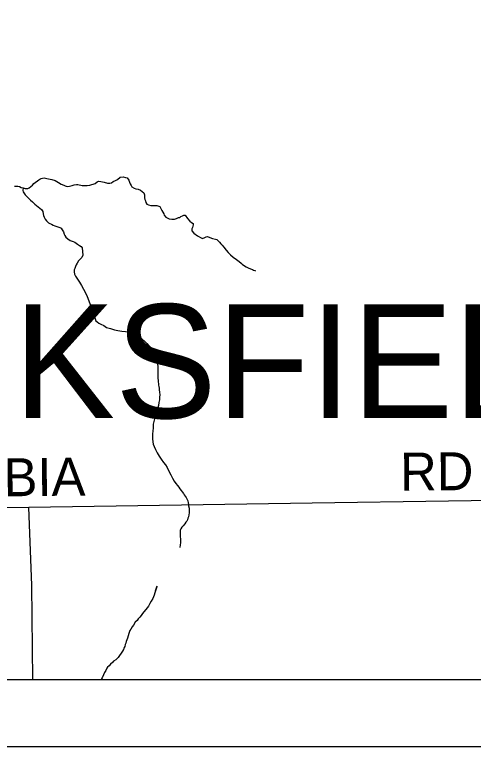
# Model space of a CAD drawing. Extents: x 0 to 34, y 0 to 22.
# Drawn here: x 4.472 to 5.159, y 14 to 15.096 of the extents above; entities that cross this region are included whole.
import ezdxf

# ---------------------------------------------------------------- set-up
doc = ezdxf.new("R2010")
doc.units = 0
for name, color, linetype in [('GM_X_Corporation', 7, 'Continuous'), ('GM_X_County_Road', 7, 'Continuous'), ('GM_X_County_Road_Text', 7, 'Continuous'), ('GM_X_Minor_River', 7, 'Continuous'), ('GM_X_Township_Road', 7, 'Continuous'), ('GM_X_Township_Text', 7, 'Continuous'), ('SH_Data', 7, 'Continuous')]:
    doc.layers.add(name, color=color, linetype=linetype)

msp = doc.modelspace()

# ---------------------------------------------------------------- linework, layer by layer
at = {"layer": 'GM_X_Corporation'}
msp.add_lwpolyline([(2.1, 20.3879), (2.1, 14.1), (7.1335, 14.1), (7.1269, 14.4049), (7.1267, 14.4123), (7.1215, 14.6514), (7.118, 14.8105), (7.1072, 15.3824), (7.0838, 16.6084)], dxfattribs=at)
msp.add_lwpolyline([(2.1, 15.3574), (2.1, 14.1), (7.1335, 14.1), (7.1269, 14.4049), (7.1267, 14.4123), (7.1215, 14.6514), (7.118, 14.8105), (7.1072, 15.3824), (6.0415, 15.3685), (5.8313, 15.3671), (5.1944, 15.3696), (4.1554, 15.3654), (4.1534, 15.3654), (3.4135, 15.3624), (2.6127, 15.3592)], close=True, dxfattribs=at)
at = {"layer": 'GM_X_County_Road'}
msp.add_lwpolyline([(3.4637, 14.2828), (3.4705, 14.2865), (3.4834, 14.2899), (3.5484, 14.2951), (3.6062, 14.2988), (3.6339, 14.2982), (3.6511, 14.2957), (3.6628, 14.292), (3.6812, 14.2847), (3.6986, 14.2775), (3.7141, 14.2746), (3.7758, 14.2933), (3.8973, 14.3317), (3.9354, 14.344), (3.9526, 14.3483), (3.9767, 14.3512), (4.4934, 14.358), (4.9174, 14.3648), (5.3258, 14.3705), (5.4131, 14.3722), (5.5063, 14.374), (5.7673, 14.3801), (6.0754, 14.3845)], dxfattribs=at)
at = {"layer": 'GM_X_Minor_River'}
for points in [[(4.4718, 14.8387), (4.4741, 14.839), (4.4767, 14.8386), (4.479, 14.8382), (4.4817, 14.837), (4.4847, 14.8362), (4.4877, 14.8354), (4.49, 14.8354), (4.4919, 14.8354), (4.4938, 14.8361), (4.4961, 14.8384), (4.4988, 14.8403), (4.5007, 14.8429), (4.5027, 14.8444), (4.5061, 14.847), (4.508, 14.8481), (4.5099, 14.8492), (4.5119, 14.8504), (4.5138, 14.8507), (4.5164, 14.8511), (4.5202, 14.8503), (4.5274, 14.849), (4.5327, 14.8471), (4.5376, 14.8444), (4.5418, 14.842), (4.5456, 14.8405), (4.5475, 14.8393), (4.5505, 14.8385), (4.5543, 14.8388), (4.5581, 14.8399), (4.5612, 14.8407), (4.5646, 14.8414), (4.5665, 14.8414), (4.5684, 14.841), (4.571, 14.8402), (4.5733, 14.8398), (4.5763, 14.8397), (4.5805, 14.8397), (4.5847, 14.8404), (4.5927, 14.8426), (4.5954, 14.8452), (4.5973, 14.8463), (4.6011, 14.8459), (4.6061, 14.8447), (4.611, 14.8435), (4.6144, 14.8434), (4.6171, 14.8438), (4.6194, 14.8457), (4.6232, 14.8475), (4.6259, 14.849), (4.6301, 14.8524), (4.6343, 14.8527), (4.6381, 14.8519), (4.6403, 14.8511), (4.643, 14.8477), (4.6441, 14.845), (4.6452, 14.8423), (4.6463, 14.8396), (4.6474, 14.8377), (4.6508, 14.8358), (4.6535, 14.835), (4.6569, 14.8342), (4.6603, 14.833), (4.6629, 14.8307), (4.6652, 14.8288), (4.6663, 14.8257), (4.6666, 14.8238), (4.6666, 14.8215), (4.6669, 14.8189), (4.6677, 14.8166), (4.6684, 14.8143), (4.6699, 14.812), (4.6726, 14.8108), (4.676, 14.81), (4.6809, 14.81), (4.6828, 14.8099), (4.6847, 14.8099), (4.6892, 14.8084), (4.6915, 14.8045), (4.6926, 14.8022), (4.6941, 14.7996), (4.6952, 14.7973), (4.6959, 14.7953), (4.6986, 14.7923), (4.7016, 14.7907), (4.7035, 14.7899), (4.7076, 14.7895), (4.7114, 14.7895), (4.7145, 14.7906), (4.7172, 14.7917), (4.7191, 14.792), (4.721, 14.7935), (4.7233, 14.7946), (4.7252, 14.7954), (4.7271, 14.7954), (4.7308, 14.7904), (4.7342, 14.7862)], [(4.4849, 14.8362), (4.4843, 14.8324), (4.4846, 14.8302), (4.4876, 14.8259), (4.491, 14.8225), (4.4932, 14.8202), (4.4955, 14.8179), (4.4985, 14.8152), (4.5023, 14.8117), (4.5072, 14.8079), (4.512, 14.8036), (4.5143, 14.8009), (4.5146, 14.7975), (4.515, 14.7948), (4.5161, 14.7922), (4.5176, 14.7895), (4.5198, 14.7868), (4.5225, 14.7841), (4.5247, 14.7829), (4.527, 14.7818), (4.5296, 14.7802), (4.5323, 14.7794), (4.5368, 14.7779), (4.5395, 14.7771), (4.5414, 14.7759), (4.5429, 14.7736), (4.5451, 14.7702), (4.5462, 14.7671), (4.5473, 14.7648), (4.5488, 14.7625), (4.5518, 14.7598), (4.5552, 14.7575), (4.5598, 14.7559), (4.562, 14.7551), (4.5643, 14.7536), (4.5662, 14.7517), (4.5692, 14.7497), (4.5714, 14.7486), (4.5729, 14.7466), (4.574, 14.7356), (4.5724, 14.7322), (4.5697, 14.7292), (4.5674, 14.7269), (4.5654, 14.7235), (4.5643, 14.7209), (4.5631, 14.7183), (4.5619, 14.7156), (4.5611, 14.7133), (4.5611, 14.7103), (4.5614, 14.7072), (4.5629, 14.7038), (4.5659, 14.6996), (4.5693, 14.695), (4.5723, 14.69), (4.5752, 14.6847), (4.5782, 14.6789), (4.5804, 14.6736), (4.583, 14.6671), (4.5852, 14.6617), (4.5874, 14.656), (4.5893, 14.6503), (4.5911, 14.6446), (4.5926, 14.64), (4.5937, 14.6369), (4.5956, 14.6354), (4.5978, 14.6338), (4.6012, 14.6323), (4.6054, 14.63), (4.6095, 14.6272), (4.6156, 14.6257), (4.6213, 14.6237), (4.6266, 14.6225), (4.6326, 14.6216), (4.638, 14.6212), (4.6425, 14.6204), (4.6471, 14.6196), (4.6516, 14.6176), (4.6554, 14.6157), (4.6588, 14.613), (4.6625, 14.6103), (4.667, 14.6064), (4.6701, 14.6033), (4.673, 14.5995), (4.676, 14.5961), (4.6783, 14.593), (4.6831, 14.5815), (4.6846, 14.5773), (4.686, 14.5727), (4.6864, 14.5682), (4.6863, 14.5629), (4.6862, 14.5591), (4.6866, 14.5549), (4.6865, 14.5511), (4.6869, 14.548), (4.6868, 14.5454), (4.6872, 14.5431), (4.6875, 14.5408), (4.6879, 14.5389), (4.6882, 14.5362), (4.6886, 14.5336), (4.6889, 14.5305)], [(4.7342, 14.7862), (4.7369, 14.7842), (4.7391, 14.7827), (4.7391, 14.7808), (4.7383, 14.777), (4.7375, 14.7747), (4.7375, 14.7717), (4.7405, 14.7682), (4.7457, 14.7644), (4.7514, 14.7612), (4.7533, 14.7605), (4.7567, 14.7619), (4.759, 14.7631), (4.7609, 14.7634), (4.7643, 14.7619), (4.7685, 14.7603), (4.7727, 14.7595), (4.7749, 14.7591), (4.7787, 14.7548), (4.7809, 14.7525), (4.7828, 14.7502), (4.7851, 14.7472), (4.7888, 14.7429), (4.7918, 14.7395), (4.7952, 14.736), (4.7993, 14.7325), (4.8042, 14.7291), (4.8084, 14.726), (4.811, 14.7237), (4.8129, 14.7221), (4.8163, 14.7194), (4.8185, 14.7179), (4.8216, 14.7163), (4.8253, 14.7148), (4.828, 14.714), (4.8299, 14.7128), (4.8318, 14.7124), (4.8325, 14.712)], [(4.6889, 14.5305), (4.6893, 14.5263), (4.6888, 14.5229), (4.6888, 14.5191), (4.688, 14.515), (4.6872, 14.5104), (4.6856, 14.5047), (4.684, 14.4994), (4.6824, 14.4945), (4.6812, 14.4903), (4.6804, 14.4862), (4.6796, 14.4824), (4.6792, 14.4771), (4.6787, 14.4721), (4.6783, 14.4679), (4.6783, 14.4645), (4.6786, 14.4603), (4.6789, 14.4562), (4.6796, 14.4527), (4.6807, 14.4489), (4.683, 14.4443), (4.6856, 14.4394), (4.6882, 14.4344), (4.6912, 14.4302), (4.6949, 14.4252), (4.6979, 14.4214), (4.7005, 14.4175), (4.7031, 14.4122), (4.7057, 14.4068), (4.7083, 14.4015), (4.7109, 14.3973), (4.7135, 14.3934), (4.7158, 14.3904), (4.718, 14.388), (4.7195, 14.3858), (4.7247, 14.3785), (4.7259, 14.3766), (4.7274, 14.3746), (4.7289, 14.3727), (4.73, 14.3704), (4.7311, 14.3678), (4.7318, 14.3647), (4.7321, 14.362), (4.7325, 14.3601), (4.7332, 14.3567), (4.7332, 14.3548), (4.7332, 14.3521), (4.7331, 14.3495), (4.7327, 14.3465), (4.7323, 14.3438), (4.7315, 14.3415), (4.7307, 14.3393), (4.73, 14.3374), (4.7284, 14.3355), (4.7269, 14.3332), (4.7245, 14.3302), (4.7222, 14.328), (4.7207, 14.3257), (4.7199, 14.3238), (4.7199, 14.3219), (4.7199, 14.3196), (4.7198, 14.3166), (4.7198, 14.3135), (4.7201, 14.3105), (4.7201, 14.3082), (4.7201, 14.3059), (4.7196, 14.3006), (4.7192, 14.2987), (4.7192, 14.298)], [(4.6847, 14.2399), (4.6827, 14.233), (4.6847, 14.2387), (4.6827, 14.233), (4.6819, 14.23), (4.6807, 14.2262), (4.6788, 14.2213), (4.6764, 14.2172), (4.6745, 14.2141), (4.6722, 14.21), (4.6683, 14.2047), (4.6656, 14.2013), (4.6633, 14.1987), (4.6613, 14.1961), (4.6594, 14.1934), (4.6571, 14.1912), (4.6552, 14.1885), (4.6525, 14.1859), (4.6501, 14.1817), (4.6482, 14.1791), (4.6459, 14.1753), (4.6443, 14.1735), (4.6428, 14.1689), (4.642, 14.1655), (4.6408, 14.1621), (4.64, 14.1594), (4.6392, 14.1572), (4.6384, 14.1545), (4.6376, 14.1523), (4.6368, 14.1496), (4.6357, 14.147), (4.6349, 14.1451), (4.6337, 14.1424), (4.6268, 14.133), (4.6233, 14.1296), (4.6202, 14.1278), (4.6187, 14.1255), (4.6156, 14.1233), (4.6133, 14.1206), (4.611, 14.1187), (4.6098, 14.1169), (4.6083, 14.1138), (4.6063, 14.1108), (4.6048, 14.107), (4.6028, 14.1025), (4.6014, 14.1)]]:
    msp.add_lwpolyline(points, dxfattribs=at)
at = {"layer": 'GM_X_Township_Road'}
msp.add_lwpolyline([(4.4994, 14.1), (4.4975, 14.241), (4.4934, 14.358)], dxfattribs=at)
at = {"layer": 'SH_Data'}
for p, q in [((2.1, 14.1), (8.9, 14.1)), ((2, 14), (9, 14))]:
    msp.add_line(p, q, dxfattribs=at)

# ---------------------------------------------------------------- texts
at = {"layer": 'GM_X_County_Road_Text'}
for s, rotation, p in [('RD', 0.4937, (5.0495, 14.3828)), ('ZENOBIA', 0.6212, (4.2446, 14.372))]:
    msp.add_text(s, height=0.05682, rotation=rotation, dxfattribs=at).set_placement(p)
at = {"layer": 'GM_X_Township_Text'}
msp.add_text('CLARKSFIELD', height=0.170455, rotation=0, dxfattribs=at).set_placement((3.8623, 14.4915))

doc.saveas('drawing.dxf')
